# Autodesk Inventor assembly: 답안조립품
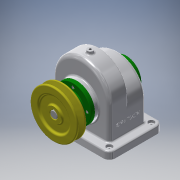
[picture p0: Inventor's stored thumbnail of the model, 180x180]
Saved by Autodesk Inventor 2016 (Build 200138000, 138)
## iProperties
Created: 2017-11
Part Number: 답안조립품
Material: 일반
Document SubType Name: Assembly
Designer: USER
Author: USER
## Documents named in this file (14)
- C:\Users\USER\Desktop\471107V1031\답안조립품.iam
- C:\Users\USER\Desktop\471107V1031\본체.ipt
- C:\Users\USER\Desktop\471107V1031\V-벨트풀리.ipt
- C:\Users\USER\Desktop\471107V1031\뒤커버.ipt
- C:\Users\USER\Desktop\471107V1031\멈춤나사 - M4 x 10.ipt
- 멈춤나사 - M4 x 10.ipt
- C:\Users\USER\Desktop\471107V1031\베어링 6002.ipt
- C:\Users\USER\Desktop\471107V1031\볼트 M3 x 8.ipt
- C:\Users\USER\Desktop\471107V1031\스퍼기어.ipt
- C:\Users\USER\Desktop\471107V1031\앞커버.ipt
- C:\Users\USER\Desktop\471107V1031\오일 실 15 30 7.ipt
- C:\Users\USER\Desktop\471107V1031\축.ipt
- C:\Users\USER\Desktop\471107V1031\키 - 5 x 5 x 18.ipt
- C:\Users\USER\Desktop\471107V1031\키 - 6 x 6 x 22.ipt
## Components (1 placed, 1 different names)
1. V-벨트풀리:1 — 플러쉬:1
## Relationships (1: Flush 1)
- 플러쉬:1 [Flush]: V-벨트풀리:1
